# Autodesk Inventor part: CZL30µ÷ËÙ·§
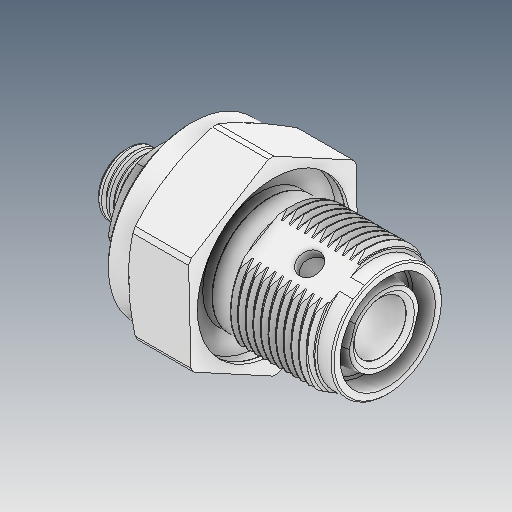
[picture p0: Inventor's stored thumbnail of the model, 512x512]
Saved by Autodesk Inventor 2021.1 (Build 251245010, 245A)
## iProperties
Created: 2021-05
Part Number: CZL30µ÷ËÙ·§
Material: Ogólny
Document SubType Name: Modeling
Designer: user
Density: 1 g/cm^3
Appearance: Domyślna
Author: user
Revision Number: ÈÎºÎ
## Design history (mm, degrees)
feature "ÊäÈë3"
feature "ÊäÈë6"
feature "ÊäÈë7"
node "Bryła1"
node "Bryła2"
node "Bryła3"
